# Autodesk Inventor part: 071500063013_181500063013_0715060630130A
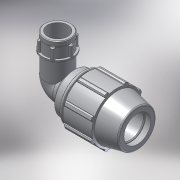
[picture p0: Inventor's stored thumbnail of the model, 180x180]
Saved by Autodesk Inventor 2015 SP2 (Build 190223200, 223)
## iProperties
Created: 2017-02
Part Number: 071500063013_181500063013_0715060630130A
Material: PVC-Piping
Description: PLASSON 90° ELBOW FEMALE ADAPTOR 63-1.1/4"
Document SubType Name: Modeling
Designer: KIM
Mass: 92.6774 g
Surface Area: 199.44 cm^2
Volume: 66.1981 cm^3
Density: 1.4 g/cm^3
Appearance: Smooth - White
Author: KIM
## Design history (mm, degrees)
derived "07150.ipt"
feature "Solid1::07150.ipt"
tag "TaggingFeature1"
body "Solid1"
other parameters: "d2" = 63, "d4" = 13.5, "d5" = 40.5, "d7" = 113, "d9" = 23.14286, "d11" = 5.4, "d13" = 120 deg, "d14" = 81.9, "d15" = 12 deg, "d16" = 98.31, "d18" = 3.15, "d19" = 35 deg, "d20" = 17.5 deg, "d21" = 105.09, "d23" = 0, "d25" = 360 deg, "d27" = 2.26, "d33" = 1.26, "d42" = 59.94, "d43" = 3.39, "d46" = 1.89, "d51" = 162, "d68" = 5.4, "d72" = 65, "d73" = 50.6376, "d74" = 25, "d75" = 58.23324, "d76" = 38.952, "d77" = 27.5, "d79" = 15.5808, "d80" = 1.16856, "d83" = 0, "d84" = 0, "d91" = 84.75, "d94" = 38.952, "d95" = 27.2664, "d96" = 13.5, "d97" = 50 deg, "d98" = 35.0568, "d99" = 0.5, "d100" = 0.5, "d101" = 8.33333, "d102" = 50.6376, "d103" = 21.25, "d104" = 0, "d108" = 360 deg, "d110" = 1.51913, "d_" = 63, "E_" = 113, "A_" = 162, "l_2" = 25, "A_1" = 65, "Rp_" = 38.952, "d105" = 7.59564
